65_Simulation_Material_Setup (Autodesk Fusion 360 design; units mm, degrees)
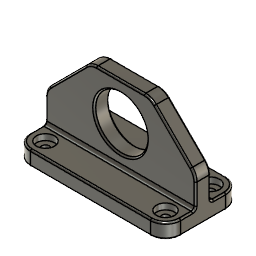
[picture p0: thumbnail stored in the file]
part number: 2026-07-20-13-25-26-316
sketch "Sketch1" plane through (0, 0, 0) normal (0, 1, 0) x axis (1, 0, 0)
  line L1 (-50, 25) -> (50, 25)
  line L2 (-50, -25) -> (-50, 25)
  line L3 (50, -25) -> (-50, -25)
  line L4 (50, 25) -> (50, -25)
  line L5 (-50, -25) -> (50, 25)
  line L6 (50, -25) -> (-50, 25)
  point P6 (0, 0)
  point P1 (0, 0)
  point P4 (-50, -25)
  point P5 (50, -25)
  point P3 (-50, 25)
  horizontal L1
  perpendicular L1 L2
  parallel L1 L3
  parallel L2 L4
  coincident L5 P6
  coincident L6 P6
  coincident P1 P6
  dimension "d2" distance P4 P5 = 100
  dimension "d3" distance P3 P4 = 50
extrude "Extrude1" new body sketch "Sketch1" profile of L1 L2 L3 L4 distance 10
sketch "Sketch2" plane through (0, 0, -25) normal (0, 0, -1) x axis (1, 0, 0)
  line L1 (-50, -5) -> (-50, 5)
  line L2 (50, -5) -> (-50, -5)
  line L3 (50, 5) -> (50, -5)
  line L4 (-50, 5) -> (50, 5)
  line L5 (-50, -25) -> (50, -25)
  line L6 (-50, 25) -> (-50, -25)
  line L7 (50, 25) -> (-50, 25)
  line L8 (50, -25) -> (50, 25)
  line L9 (-50, 25) -> (50, -25)
  line L10 (50, 25) -> (-50, -25)
  point P10 (0, 0)
  point P1 (0, 0)
  point P5 (50, 5)
  point P7 (-50, -25)
  point P8 (-50, 25)
  horizontal L5
  perpendicular L5 L6
  parallel L5 L7
  parallel L6 L8
  coincident L9 P10
  coincident L10 P10
  coincident P1 P10
  coincident P5 L8
  dimension "d6" distance P7 P8 = 50
extrude "Extrude2" add sketch "Sketch2" profile of L1 L2 L3 L4 L5 L6 L7 L8 along normal blind 10
chamfer "Chamfer1" sketch "Sketch2" distance 30
sketch "Sketch3" plane through (0, -5, 0) normal (0, -1, 0) x axis (1, 0, 0)
  line L1 (20, 25) -> (50, -5)
  line L2 (-20, 25) -> (20, 25)
  line L3 (-50, -5) -> (-20, 25)
  line L4 (-50, -25) -> (-50, -5)
  line L5 (50, -25) -> (-50, -25)
  line L6 (50, -5) -> (50, -25)
  circle C1 centre (0, 0) radius 17.5
  point P1 (0, 0)
  point P8 (0, 0)
  coincident P1 P8
  dimension "d10" diameter C1 = 35
extrude "Extrude3" cut sketch "Sketch3" profile of C1 no distance stored
fillet "Fillet1" radius 10
fillet "Fillet2" radius 10
sketch "Sketch4" plane through (0, 0, -25) normal (0, 0, 1) x axis (-1, 0, 0)
  line L1 (50, -5) -> (50, -15)
  line L2 (-50, -5) -> (50, -5)
  line L3 (-50, -15) -> (-50, -5)
  line L4 (40, -25) -> (-40, -25)
  line L5 (-40, 25) -> (40, 25)
  line L6 (-50, 5) -> (-50, 15)
  line L7 (50, 5) -> (-50, 5)
  line L8 (50, 15) -> (50, 5)
  arc A1 centre (40, -15) radius 10 clockwise from (50, -15) to (40, -25)
  arc A2 centre (-40, -15) radius 10 clockwise from (-40, -25) to (-50, -15)
  arc A3 centre (40, 15) radius 10 clockwise from (40, 25) to (50, 15)
  arc A4 centre (-40, 15) radius 10 clockwise from (-50, 15) to (-40, 25)
  point P9 (-40, -15)
  point P18 (-40, -15)
  point P4 (40, -15)
  point P19 (40, -15)
  point P12 (40, 15)
  point P20 (40, 15)
  point P15 (-40, 15)
  point P21 (-40, 15)
  coincident P9 P18
  coincident P4 P19
  coincident P12 P20
  coincident P15 P21
hole "Hole1" sketch "Sketch2" HoleDiameter 5 TipAngle 118 CBDepth 4 CBDiameter 12
fillet "Fillet3" radius 2
fillet "Fillet4" radius 1
chamfer "Chamfer2" sketch "Sketch2" distance 1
